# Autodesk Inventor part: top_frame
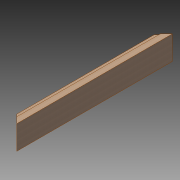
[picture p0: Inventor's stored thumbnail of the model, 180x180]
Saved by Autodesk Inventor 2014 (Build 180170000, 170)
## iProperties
Created: 2014-05
Part Number: top_frame
Material: Maple
Document SubType Name: Modeling
Designer: t_emanb
Density: 1 g/cm^3
Appearance: Maple - Solid Natural Medium Gloss
Author: t_emanb
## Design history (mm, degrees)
sketch "Sketch1"
  geometry: L1 (0, 0)-(38.1, 0); L2 (38.1, 0)-(38.1, 101.6); L3 (38.1, 101.6)-(0, 101.6); L4 (0, 101.6)-(0, 0)
  constraints: 8 end point, 2 parallel, 1 horizontal, 1 perpendicular
  dimensions: "d0" = 101.6 distance of L1.end L2.end; "d1" = 38.1 distance of L2.end L3.end
extrude "Extrusion1" new body sketch "Sketch1" distance "d2" = 660.4; taper "d3" = 0 deg
sketch "Sketch3"
  geometry: L1 (38.1, 0)-(38.1, 101.6) reference; L2 (38.1, 101.6)-(0, 101.6) reference; L3 (0, 101.6)-(0, 0) reference; L4 (12.7, 101.6)-(12.7, 98.501); L5 (12.7, 98.501)-(0, 98.501)
  constraints: 4 end point, 2 point on line, 1 parallel, 1 perpendicular
  dimensions: "d8" = 3.0988 distance of L4.start L4.end; "d9" = 25.4 distance between parallel lines of L1 L4
extrude "Extrusion3" cut sketch "Sketch3" stored distance "d10" = 660.4; taper "d11" = 0 deg
sketch "Sketch4"
  geometry: L1 (0, 98.501)-(0, 0) reference; L2 (0, 0)-(38.1, 0) reference; L3 (38.1, 101.6)-(12.7, 101.6) reference; L4 (0, 0)-(25.4, 0); L5 (25.4, 0)-(25.4, 25.4); L6 (25.4, 25.4)-(0, 25.4); L7 (38.1, 0)-(38.1, 101.6) reference
  constraints: 6 end point, 2 perpendicular, 2 point on line, 1 parallel
  dimensions: "d12" = 0 distance between parallel lines of L2 L4; "d14" = 25.4 distance of L4.end L5.end; "d18" = 12.7 distance between parallel lines of L7 L5
extrude "Extrusion4" cut sketch "Sketch4" stored distance "d15" = 660.4; taper "d16" = 0 deg
sketch "Sketch2"
  geometry: L1 (38.1, 0)-(0, 0) reference; L2 (0, 0)-(0, -660.4) reference; L3 (38.1, -660.4)-(0, -660.4) reference; L4 (38.1, -660.4)-(0, -622.3); L5 (38.1, 0)-(0, -38.1)
  constraints: 4 end point, 2 point on line
  dimensions: "d4" = 45 deg angle of L3 L4; "d5" = 45 deg angle of L1 L5
extrude "Extrusion2" cut sketch "Sketch2" stored distance "d6" = 660.4; taper "d7" = 0 deg
body "Solid1"
